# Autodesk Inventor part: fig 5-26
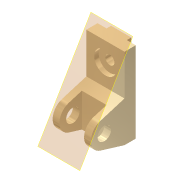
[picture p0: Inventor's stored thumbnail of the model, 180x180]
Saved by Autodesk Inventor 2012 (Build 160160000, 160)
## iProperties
Shininess: 65.0
Angle Display Precision: 2
Document Length Units: 11269
Document Angle Units: 11279
Document Time Units: 11290
Document Mass Units: 11283
Document Length Units Precision: 3
Document Angle Units Precision: 2
Compacted: False
Created: 2001-11
Part Number: fig 5-26
Document SubType Name: Modeling
Designer: Renu Muthoo
Density: 1 g/cm^3
Material: Default
Density: 0.0
Volumn: 0.0
Area: 0.0
PropertySet Name: Model Information
Control State: 0
Master: False
Checked Out: False
Author: Renu Muthoo
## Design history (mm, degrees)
node "Sketch1"
sketch "Sketch2"
  geometry: L1 (33.257, 104.664)-(33.257, -75.336); L2 (33.257, -75.336)-(8.257, -75.336); L3 (8.257, -75.336)-(-45.451, -59.045); L4 (-45.451, -1.628)-(8.257, 14.664); L5 (8.257, 14.664)-(8.257, 104.664); L6 (8.257, 104.664)-(33.257, 104.664); C1 r 15 at (-36.743, -30.336); A1 r 30 centre (-36.743, -30.336) between (-45.451, -1.628) and (-45.451, -59.045)
  constraints: 12 end point, 2 centre point, 2 equal length, 2 parallel, 2 point on circle, 2 tangent, 1 coincident, 1 perpendicular, 1 vertical
  dimensions: "d0" = 180 distance of L1.start L1.end; "d1" = 30 radius of A1; "d2" = 25 distance of L5.end L1.start; "d3" = 45 distance from line of L2 A1.centre; "d4" = 70 distance from line of L1 A1.centre; "d5" = 30 diameter of C1
extrude "Extrusion1" new body sketch "Sketch2" distance "d6" = 85; taper "d7" = 0 deg
workplane "Work Plane1"
sketch "Sketch3"
  geometry: L1 (15, 62.364)-(70, 62.364); L2 (70, 62.364)-(70, -52.386); L3 (70, -52.386)-(15, -52.386); L4 (15, -52.386)-(15, 62.364); L5 (0, -45)-(0, -28.708) reference
  constraints: 8 end point, 2 parallel, 1 horizontal, 1 perpendicular
  dimensions: "d8" = 55 distance of L1.start L1.end; "d9" = 15 distance between parallel lines of L5 L4
extrude "Extrusion2" cut sketch "Sketch3" distance "d10" = 50; taper "d11" = 0 deg
sketch "Sketch4"
  geometry: L1 (0, 25)-(85, 25) reference; L2 (0, 0)-(0, 25) reference; L3 (20, 25)-(65, 25); L4 (65, 25)-(65, 35); L5 (65, 35)-(20, 35); L6 (20, 35)-(20, 25)
  constraints: 8 end point, 2 parallel, 1 horizontal, 1 perpendicular, 1 point on line
  dimensions: "d12" = 45 distance of L4.end L5.end; "d13" = 10 distance of L3.end L4.end; "d14" = 20 distance between parallel lines of L2 L6
extrude "Extrusion3" join sketch "Sketch4" stored distance "d15" = 50; taper "d16" = 0 deg
sketch "Sketch5"
  geometry: L1 (85, 0)-(85, 90) reference; L2 (0, 90)-(85, 90) reference; 1 further point
  dimensions: "d17" = 42 distance from line of L2 point (42.5, 48); "d18" = 42.5 distance from line of L1 point (42.5, 48)
hole "Hole1" sketch "Sketch5" at (42.5, 48) diameter "d19" = 20; stored, may be unused: countersink angle "d23" = 82 deg, drill point angle "d25" = 118 deg; dims "d20" = 6, "d21" = 50, "d22" = 10, "d24" = 8
workplane "Work Plane12"
body "Solid1"
